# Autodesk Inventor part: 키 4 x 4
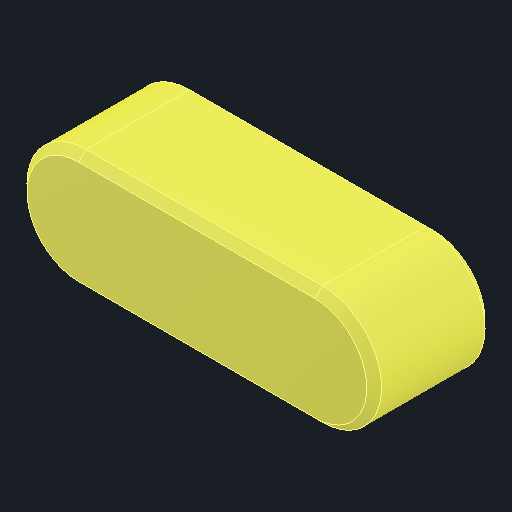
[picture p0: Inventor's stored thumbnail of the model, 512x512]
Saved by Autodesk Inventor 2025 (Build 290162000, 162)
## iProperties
Created: 2025-08
Part Number: 키 4 x 4
Material: 강철, 연강
Description: 키 및 해당 키홈
Document SubType Name: Modeling
Designer: infra012
Density: 7.86 g/cm^3
Appearance: 기본값
Author: jhkim
Sending System: Autodesk Inventor 2026
Preprocessor: ST-DEVELOPER v20.1
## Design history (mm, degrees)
sketch "스케치1"
  geometry: 1 further point
  constraints: 1 other
feature "Solid1"
node "솔리드1"
